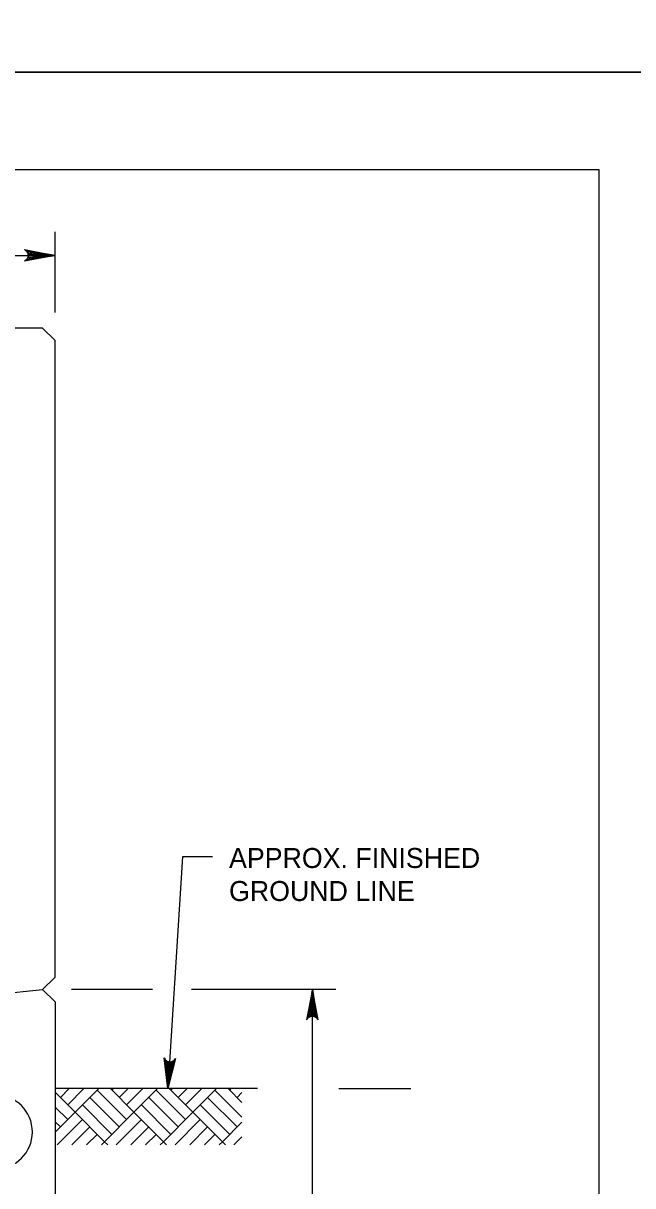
# Model space of a CAD drawing. Extents: x 638167 to 640248, y 296544 to 298920.
# Drawn here: x 639744.3 to 639838, y 297561.4 to 297740 of the extents above; entities that cross this region are included whole.
import ezdxf

# ---------------------------------------------------------------- set-up
doc = ezdxf.new("R2010")
doc.units = 0
doc.layers.add('1', color=7, linetype='Continuous')
doc.layers.add('PLT-BNDY', color=7, linetype='Continuous')

msp = doc.modelspace()

# ---------------------------------------------------------------- linework, layer by layer
at = {"layer": '1'}
for p, q in [((639832.78, 297717.48), (639046.78, 297717.48)), ((639832.78, 297153.48), (639832.78, 297717.48)), ((639749.22, 297695.55), (639749.22, 297707.94)), ((639697.78, 297704.31), (639749.22, 297704.31)), ((639747.31, 297693.14), (639720.84, 297693.14)), ((639749.22, 297691.23), (639747.31, 297693.14)), ((639749.22, 297593.44), (639749.22, 297691.23)), ((639768.8, 297611.91), (639766.56, 297576.3)), ((639773.42, 297611.91), (639768.8, 297611.91)), ((639749.22, 297593.44), (639747.31, 297591.54)), ((639697.78, 297586.46), (639747.31, 297591.54)), ((639749.22, 297589.63), (639747.31, 297591.54)), ((639764.19, 297591.54), (639751.74, 297591.54)), ((639792.33, 297591.54), (639770.19, 297591.54)), ((639788.74, 297521.68), (639788.74, 297591.54)), ((639749.22, 297589.63), (639749.22, 297521.68)), ((639780.33, 297576.3), (639749.22, 297576.3)), ((639752.29, 297572.67), (639749.22, 297575.73)), ((639750.03, 297574.93), (639751.39, 297576.3)), ((639751.16, 297573.8), (639753.66, 297576.3)), ((639752.29, 297572.67), (639755.92, 297576.3)), ((639759.08, 297570.4), (639754.55, 297574.93)), ((639760.21, 297571.53), (639755.68, 297576.06)), ((639761.34, 297572.67), (639757.71, 297576.3)), ((639757.95, 297576.06), (639758.18, 297576.3)), ((639759.08, 297574.93), (639760.44, 297576.3)), ((639760.21, 297573.8), (639762.71, 297576.3)), ((639761.34, 297572.67), (639764.97, 297576.3)), ((639768.13, 297570.4), (639763.6, 297574.93)), ((639769.26, 297571.53), (639764.73, 297576.06)), ((639770.39, 297572.67), (639766.76, 297576.3)), ((639767, 297576.06), (639767.23, 297576.3)), ((639768.13, 297574.93), (639769.5, 297576.3)), ((639769.26, 297573.8), (639771.76, 297576.3)), ((639770.39, 297572.67), (639774.02, 297576.3)), ((639777.18, 297570.4), (639772.65, 297574.93)), ((639777.93, 297571.91), (639773.78, 297576.06)), ((639777.93, 297574.18), (639775.81, 297576.3)), ((639776.05, 297576.06), (639776.28, 297576.3)), ((639777.18, 297574.93), (639777.93, 297575.68)), ((639792.79, 297576.3), (639803.84, 297576.3)), ((639751.16, 297571.53), (639749.22, 297573.47)), ((639757.95, 297569.27), (639753.42, 297573.8)), ((639767, 297569.27), (639762.47, 297573.8)), ((639776.05, 297569.27), (639771.52, 297573.8)), ((639749.22, 297569.6), (639752.29, 297572.67)), ((639750.03, 297570.4), (639749.22, 297571.21)), ((639749.54, 297567.65), (639753.42, 297571.53)), ((639756.81, 297568.14), (639752.29, 297572.67)), ((639756.81, 297568.14), (639761.34, 297572.67)), ((639758.59, 297567.65), (639762.47, 297571.53)), ((639765.87, 297568.14), (639761.34, 297572.67)), ((639765.87, 297568.14), (639770.39, 297572.67)), ((639767.64, 297567.65), (639771.52, 297571.53)), ((639774.92, 297568.14), (639770.39, 297572.67)), ((639774.92, 297568.14), (639777.93, 297571.15)), ((639751.8, 297567.65), (639754.55, 297570.4)), ((639754.07, 297567.65), (639755.68, 297569.27)), ((639760.85, 297567.65), (639763.6, 297570.4)), ((639763.12, 297567.65), (639764.73, 297569.27)), ((639769.91, 297567.65), (639772.65, 297570.4)), ((639772.17, 297567.65), (639773.78, 297569.27)), ((639756.33, 297567.65), (639756.81, 297568.14)), ((639757.3, 297567.65), (639756.81, 297568.14)), ((639765.38, 297567.65), (639765.87, 297568.14)), ((639766.35, 297567.65), (639765.87, 297568.14)), ((639774.43, 297567.65), (639774.92, 297568.14)), ((639775.4, 297567.65), (639774.92, 297568.14)), ((639776.69, 297567.65), (639777.93, 297568.89))]:
    msp.add_line(p, q, dxfattribs=at)
for points in [[(639749.22, 297704.31), (639744.52, 297703.43), (639744.7, 297703.56), (639744.88, 297703.68), (639744.98, 297703.84), (639745.07, 297704), (639745.1, 297704.16), (639745.12, 297704.31), (639745.1, 297704.47), (639745.07, 297704.63), (639744.98, 297704.79), (639744.88, 297704.94), (639744.7, 297705.07), (639744.52, 297705.2), (639749.22, 297704.31), (639744.7, 297705.07), (639744.88, 297704.94), (639749.22, 297704.31), (639744.98, 297704.79), (639745.07, 297704.63), (639749.22, 297704.31), (639745.1, 297704.47), (639745.12, 297704.31), (639749.22, 297704.31), (639745.1, 297704.16), (639745.07, 297704), (639749.22, 297704.31), (639744.98, 297703.84), (639744.88, 297703.68), (639749.22, 297704.31), (639744.7, 297703.56)], [(639788.74, 297591.54), (639787.86, 297586.84), (639787.99, 297587.02), (639788.11, 297587.2), (639788.27, 297587.29), (639788.43, 297587.39), (639788.58, 297587.41), (639788.74, 297587.44), (639788.9, 297587.41), (639789.06, 297587.39), (639789.21, 297587.29), (639789.37, 297587.2), (639789.5, 297587.02), (639789.62, 297586.84), (639788.74, 297591.54), (639789.5, 297587.02), (639789.37, 297587.2), (639788.74, 297591.54), (639789.21, 297587.29), (639789.06, 297587.39), (639788.74, 297591.54), (639788.9, 297587.41), (639788.74, 297587.44), (639788.74, 297591.54), (639788.58, 297587.41), (639788.43, 297587.39), (639788.74, 297591.54), (639788.27, 297587.29), (639788.11, 297587.2), (639788.74, 297591.54), (639787.99, 297587.02)], [(639766.56, 297576.3), (639765.98, 297581.04), (639766.09, 297580.85), (639766.2, 297580.66), (639766.35, 297580.56), (639766.51, 297580.46), (639766.66, 297580.42), (639766.82, 297580.38), (639766.98, 297580.4), (639767.13, 297580.42), (639767.3, 297580.5), (639767.46, 297580.58), (639767.6, 297580.76), (639767.73, 297580.93), (639766.56, 297576.3), (639767.6, 297580.76), (639767.46, 297580.58), (639766.56, 297576.3), (639767.3, 297580.5), (639767.13, 297580.42), (639766.56, 297576.3), (639766.98, 297580.4), (639766.82, 297580.38), (639766.56, 297576.3), (639766.66, 297580.42), (639766.51, 297580.46), (639766.56, 297576.3), (639766.35, 297580.56), (639766.2, 297580.66), (639766.56, 297576.3), (639766.09, 297580.85)]]:
    msp.add_lwpolyline(points, dxfattribs=at)
msp.add_arc((639740.02, 297569.63), 5.71, 275.6517, 95.6517, dxfattribs=at)
at = {"layer": 'PLT-BNDY'}
for points in [[(639007.78, 298326.48), (639848.78, 298326.48), (639848.78, 297732.48), (639007.78, 297732.48)], [(639007.78, 297732.48), (639848.78, 297732.48), (639848.78, 297138.48), (639007.78, 297138.48)]]:
    msp.add_lwpolyline(points, close=True, dxfattribs=at)

# ---------------------------------------------------------------- texts
at = {"layer": '1'}
for s, p in [('APPROX. FINISHED', (639775.94, 297610.19)), ('GROUND LINE', (639775.94, 297605.12))]:
    msp.add_text(s, height=3.072, rotation=360, dxfattribs=at).set_placement(p)

doc.saveas('drawing.dxf')
